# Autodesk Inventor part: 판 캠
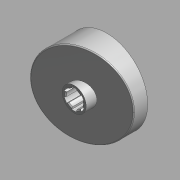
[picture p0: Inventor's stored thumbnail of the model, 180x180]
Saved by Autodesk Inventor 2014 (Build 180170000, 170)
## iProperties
Created: 2015-11
Part Number: 판 캠
Document SubType Name: 모델링
Designer: mdu
Material: 강철, 연강
Density: 7.86 g/cm^3
Appearance: 알루미늄 - 평지
Mass: 682.455 g
Surface Area: 331.303 cm^2
Volume: 86.8264 cm^3
변환 표준: STEP AP214IS
파일 이름: C:\Users\SeoGD\Desktop\?쒗뿕\??stp
전처리기: Build: 253, Release: 2010 SP1 - Date: Wed 07/29/2009
전송 단위: 밀리미터
불확실성: 0.01
Author: mdu
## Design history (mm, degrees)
node "작업 평면4"
sketch "스케치1"
  geometry: C1 r 44.5 at (0, 0); 1 further point
  constraints: 1 centre point, 1 coincident
  dimensions: "d25" = 89 diameter of C1
extrude "돌출1" new body sketch "스케치1" distance "d1" = 40; taper "d2" = 0 deg
sketch "스케치2"
  geometry: L1 (-44.5, 15)-(44.5, 38.847); L2 (-44.5, 0)-(-44.5, 40) reference; L3 (-44.5, 40)-(44.5, 40) reference; L4 (44.5, 0)-(44.5, 40) reference; 1 further point
  constraints: 2 end point, 2 point on line
  dimensions: "d26" = 15 distance of L2.start L1.start; "d27" = 75 deg angle of L1 L2
extrude "돌출2" cut sketch "스케치2" stored distance "d5" = 40; taper "d6" = 0 deg
node "작업 평면1"
sketch "스케치3"
  geometry: C1 r 13 at (0, 0); 1 further point
  constraints: 1 centre point, 1 coincident
  dimensions: "d9" = 26 diameter of C1
extrude "돌출3" join sketch "스케치3" distance "d10" = 38; taper "d11" = 0 deg
hole "구멍1" diameter "d14" = 18; stored, may be unused: countersink angle "d18" = 90 deg, drill point angle "d20" = 118 deg; dims "d12" = 10, "d13" = 10, "d15" = 6, "d16" = 4, "d17" = 2, "d19" = 8
feature "쉘2" dims "d29" = 5
sketch "스케치6"
  geometry: C1 r 17.5 at (0, 0); C2 r 14 at (0, 0) reference; 1 further point
  constraints: 1 centre point, 1 coincident
  dimensions: "d28" = 35 diameter of C1
extrude "돌출4" join sketch "스케치6" stored distance "d30" = 38; taper "d31" = 0 deg
fillet "모깎기1" dims "d32" = 3
chamfer "모따기1" distance "d21" = 1; stored, may be unused: second distance "d22" = 2, angle "d23" = 45 deg
sketch "스케치7"
  geometry: L1 (-12.374, 12.374)-(-27.931, 27.931); A1 r 39.5 centre (0, 0) between (-27.931, 27.931) and (0, 39.5) reference; 2 further points
  constraints: 2 end point, 2 point on circle, 1 point on line, 1 vertical alignment, 2 other
  dimensions: "d33" = 45 deg dimension on point (0, 0) L1.start A1.end
feature "리브1" sketch "스케치7" dims "d34" = 5, "d35" = 1, "d36" = 0
fillet "모깎기2" dims "d37" = 3
sketch "스케치8"
  geometry: L1 (2.5, 10.712)-(2.5, 8.646); L2 (-2.5, 10.712)-(-2.5, 8.646); A1 r 11 centre (0, 0) between (2.5, 10.712) and (-2.5, 10.712); A2 r 9 centre (0, 0) between (2.5, 8.646) and (-2.5, 8.646) reference; 1 further point
  constraints: 4 end point, 4 point on circle, 2 parallel, 1 centre point, 1 coincident, 1 vertical
  dimensions: "d41" = 22 diameter of A1; "d42" = 5 distance between parallel lines of L1 L2
extrude "돌출5" cut sketch "스케치8" stored distance "d43" = 38; taper "d44" = 0 deg
fillet "모깎기3" dims "d48" = 1
node "솔리드1"
node "솔리드 본체"
node "곡면 본체"
pattern_circular "원형 패턴1" dims angle "d39" = 360 deg
pattern_circular "원형 패턴2" dims angle "d46" = 360 deg
node "솔리드2"
